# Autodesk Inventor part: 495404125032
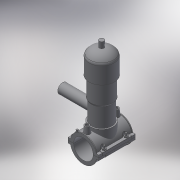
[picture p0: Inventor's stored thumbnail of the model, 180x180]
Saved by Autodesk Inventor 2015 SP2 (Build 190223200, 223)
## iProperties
Created: 2017-07
Part Number: 495404125032
Material: Generic
Description: PLASSON TAPPING VALVE 125-32
Document SubType Name: Modeling
Designer: KIM
Density: 1 g/cm^3
Appearance: Default
Author: KIM
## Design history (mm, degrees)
derived "495404-4954S4.ipt"
feature "Solid1::495404-4954S4.ipt"
feature "Solid2::495404-4954S4.ipt"
tag "TaggingFeature1"
body "Solid1"
body "Solid2"
other parameters: "d0" = 125, "d2" = 162, "d3" = 31.25, "d4" = 118, "d5" = 0, "d6" = 0.1, "d8" = 0, "d19" = 6, "d20" = 6, "d21" = 70.8, "d23" = 0, "d24" = 35.4, "d26" = 0, "d27" = 3, "d28" = 3, "d29" = 3, "d30" = 41.66667, "d31" = 6, "d32" = 0, "d33" = 0, "d34" = 0.6, "d40" = 81.25, "d47" = 124.125, "d70" = 15, "d72" = 0, "d73" = 6, "d75" = 5, "d76" = 0, "d77" = 6.25, "d78" = 92.5, "d79" = 15, "d80" = 47.2, "d82" = 5 deg, "d84" = 4, "d85" = 14, "d86" = 0, "d87" = 3, "d88" = 0, "d89" = 1, "d90" = 1, "d91" = 94.4, "d92" = 0, "d93" = 0.5, "d94" = 65.78947, "d96" = 160.9375, "d97" = 2.36, "d98" = 0, "d120" = 140 deg, "d121" = 24.228, "d122" = 20 deg, "d123" = 312.5, "d124" = 93.75, "d126" = 0, "d143" = 128.75, "d145" = 24.03846, "d149" = 1.875, "d150" = 26.44231, "d153" = 118, "d154" = 0, "d156" = 78.125, "d157" = 160 deg, "d159" = 6.25, "d161" = 1.875, "d162" = 70.8, "d163" = 0, "d164" = 62.5, "d167" = 12.5, "d168" = 76.21951, "d170" = 3, "d172" = 0, "d173" = 1, "d175" = 62.5, "d176" = 20 deg, "d177" = 8.75, "d178" = 31.25, "d180" = 0, "d183" = 12.5, "d184" = 7, "d185" = 38.35, "d186" = 38.35, "d187" = 78.125, "d188" = 9.375, "d189" = 8.75, "d190" = 0, "d191" = 117.1875, "d193" = 6.8, "d194" = 2.95, "d195" = 90 deg, "d197" = 0, "d199" = 0, "d205" = 14.64, "d206" = 81.33333, "d207" = 244, "d208" = 224.48, "d209" = 207.4, "d210" = 200.08, "d211" = 146.4, "d212" = 85.4, "d213" = 65.88, "d214" = 73.2, "d216" = 19.52, "d217" = 70.76, "d218" = 80.52, "d220" = 125, "d222" = 0, "d223" = 156.25, "d224" = 126, "d225" = 46, "d226" = 32, "d229" = 126, "d230" = 0, "d_" = 125, "B_" = 162, "H_" = 126, "L_" = 118, "d_t" = 6, "d_1" = 32, "H_1" = 46, "H_2" = 244, "d148" = 1.875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
